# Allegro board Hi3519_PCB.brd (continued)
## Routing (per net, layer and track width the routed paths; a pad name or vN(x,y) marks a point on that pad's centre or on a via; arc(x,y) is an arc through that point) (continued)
DDR3_DQ19: length 16.4
  TOP w0.127: U3.B9 v1(87.2,57.29)
  ART04 w0.127: v1(82.7,70.32) 83.1,69.92 83.1,68.28 85.2,66.18 85.2,65.6 85.64,65.15 85.64,63.03 86.38,62.3 86.38,60.27 87.81,58.84 87.81,57.9 v1(87.2,57.29)
  BOTTOM w0.127: v1(82.7,70.32) U15.F8
DDR3_DQ20: length 14.8
  TOP w0.127: U3.C7 85.57,56.31 v1(85.25,55.99)
  ART03 w0.127: v1(85.25,55.99) 85.76,56.5 85.76,57.42 86.03,57.7 86.03,58.92 84.69,60.26 84.69,62.35 84.08,62.96 84.08,64.28 83.88,64.48 83.88,64.87 83.66,65.1 83.29,65.1 83.11,65.27 83.11,65.72 82.91,65.92 81.5,65.92 v1(81.1,66.32)
  BOTTOM w0.127: U15.H3 v1(81.1,66.32)
DDR3_DQ21: length 13.8
  TOP w0.127: U3.A4 v1(83.3,57.94)
  ART04 w0.127: v1(80.3,69.51) 80.3,68.71 80.72,68.3 80.72,63.77 82.36,62.13 82.36,59.97 83.3,59.03 v1(83.3,57.94)
  BOTTOM w0.127: v1(80.3,69.51) U15.H8
DDR3_DQ22: length 9.1
  TOP w0.127: U3.B3 v1(82.65,57.29)
  BOTTOM w0.127: v1(82.65,57.29) 82.48,57.46 82.48,59.35 81.13,60.7 81.13,64.74 U15.G2
DDR3_DQ23: length 14.7
  TOP w0.127: U3.C5 v1(84.6,56.64)
  ART04 w0.127: v1(81.92,67.6) 82.32,67.19 82.32,64.38 83.13,63.58 83.13,60.28 84.1,59.3 84.1,57.14 v1(84.6,56.64)
  BOTTOM w0.127: v1(81.92,67.6) 81.67,67.6 80.7,68.57 U15.H7
DDR3_DQ24: length 16.9
  TOP w0.127: U3.C10 v1(87.2,55.99)
  ART04 w0.127: v1(84.3,69.51) 84.74,69.08 84.74,68.68 87.2,66.21 87.2,60.57 88.55,59.22 88.55,57.34 v1(87.2,55.99)
  BOTTOM w0.127: v1(84.3,69.51) 83.9,69.11 U15.D7
DDR3_DQ25: length 14.4
  TOP w0.127: U3.C9 86.87,56.32 v1(87.2,56.64)
  ART04 w0.127: v1(87.2,56.64) 88.17,57.61 88.17,59.02 86.76,60.43 86.76,62.56 86.28,63.04 86.28,66.47 85.58,67.17 v1(84.99,67.17)
  BOTTOM w0.127: v1(84.99,67.17) 84.7,66.88 U15.C3
DDR3_DQ26: length 19.8
  TOP w0.127: U3.A9 v1(87.2,57.94)
  BOTTOM w0.127: U15.C8 85.12,70.33 85.12,71.26 85.5,71.64 86.26,71.64 87.15,70.75 87.15,68.33 89.72,65.76 89.72,59.79 87.86,57.94 v1(87.2,57.94)
DDR3_DQ27: length 9.3
  TOP w0.127: U3.B8 v1(86.55,57.29)
  ART04 w0.127: v1(86.55,57.29) 86.6,57.34 86.6,59.15 85.29,60.46 85.29,62.63 84.87,63.06 84.87,63.93 85.1,64.16 v1(85.1,64.71)
  BOTTOM w0.127: U15.C2 v1(85.1,64.71)
DDR3_DQ28: length 16.2
  TOP w0.127: U3.C6 84.92,56.31 v1(85.25,56.64)
  BOTTOM w0.127: U15.A7 86.3,68.1 88.95,65.45 88.95,60.11 87.84,58.99 86.77,58.99 86.52,58.74 86.52,58.33 85.8,57.62 85.8,57.19 v1(85.25,56.64)
DDR3_DQ29: length 9.5
  TOP w0.127: U3.B4 v1(83.3,57.29)
  BOTTOM w0.127: U15.A2 85.91,64.72 85.91,63.41 85.37,62.88 85.37,60.51 83.75,58.88 83.75,57.74 v1(83.3,57.29)
DDR3_DQ30: length 16.8
  TOP w0.127: v1(87.03,58.59) 86.22,57.79 U3.A8
  BOTTOM w0.127: v1(87.03,58.59) 87.97,58.59 89.34,59.95 89.34,65.6 86.77,68.17 86.77,69.99 86.49,70.27 85.86,70.27 U15.B8
DDR3_DQ31: length 13
  TOP w0.127: U3.C4 v1(83.3,55.99)
  BOTTOM w0.127: U15.A3 87.19,65.03 87.19,60.63 86.85,60.29 85.7,60.29 84.15,58.74 84.15,56.84 v1(83.3,55.99)
DDR3_DQS0_N: length 18.8
  TOP w0.109: U14.G3 81.76,68.86 81.76,68.5 82.23,68.03 82.64,68.03 82.8,67.87 82.8,67.61 82.96,67.45 83.18,67.45 83.34,67.61 83.34,67.87 83.5,68.03 87.21,68.03 90.17,65.08 90.17,57.66 U3.A14
DDR3_DQS0_P: length 18.8
  TOP w0.109: U3.B14 90.45,57.3 90.45,65.2 87.33,68.32 82.35,68.32 82.05,68.62 82.05,68.86 U14.F3
DDR3_DQS1_N: length 13.9
  TOP w0.109: U3.A12 88.86,57.65 88.86,62.51 88.72,62.65 88.44,62.65 88.3,62.8 88.3,63 88.44,63.14 88.72,63.14 88.86,63.28 88.86,63.49 88.72,63.63 88.44,63.63 88.3,63.78 88.3,63.98 88.44,64.12 88.75,64.12 88.86,64.23 88.86,64.45 86.6,66.71 85.56,66.71 85.19,66.34 85.19,66.01 85.28,65.92 U14.B7
DDR3_DQS1_P: length 13.9
  TOP w0.109: U3.B12 89.14,57.29 89.14,64.57 86.72,66.99 85.44,66.99 84.9,66.46 84.9,65.99 84.83,65.92 U14.C7
DDR3_DQS2_N: length 10.7
  TOP w0.102: U3.A7 v1(85.25,57.94)
  ART03 w0.102: v1(81.9,65.52) 82.1,65.52 82.27,65.35 82.27,63.47 82.58,63.16 82.58,61.19 83.89,59.88 83.89,59.68 83.77,59.55 83.77,59.38 83.94,59.21 84.11,59.21 84.23,59.34 84.43,59.34 85.31,58.46 85.31,58 v1(85.25,57.94)
  BOTTOM w0.114: U15.G3 v1(81.9,65.52)
DDR3_DQS2_P: length 10.7
  TOP w0.102: U3.B7 v1(85.25,57.29)
  ART03 w0.102: v1(85.25,57.29) 85.25,57.42 85.62,57.79 85.62,58.59 82.89,61.32 82.89,63.29 82.58,63.6 82.58,65.39 v1(82.7,65.51)
  BOTTOM w0.114: U15.F3 v1(82.7,65.51)
DDR3_DQS3_N: length 16.4
  TOP w0.102: U3.A5 v1(84.6,57.94)
  BOTTOM w0.109: v1(84.6,57.94) 84.6,58.02 85.1,58.51 85.3,58.51 85.45,58.36 85.66,58.36 85.8,58.5 85.8,58.71 85.65,58.86 85.65,59.06 86.08,59.49 87.45,59.49 88.46,60.5 88.46,65.21 85.15,68.51 85.15,69.01 85.26,69.11 U15.B7
DDR3_DQS3_P: length 16.4
  TOP w0.102: U3.B5 83.97,57.27 83.97,57.96 v1(84.6,58.59)
  BOTTOM w0.109: v1(84.6,58.59) 84.77,58.59 84.83,58.65 85.96,59.78 87.33,59.78 88.17,60.62 88.17,65.09 84.87,68.39 84.87,68.95 U15.C7
DDR3_ODT: length 20.9
  TOP w0.127: U3.D3 v1(82.65,55.99) ; v1(79.2,67.13) 78.82,67.51 78.82,68.82 78.73,68.9 78.73,70.35 U14.K1
  ART04 w0.127: v1(82.65,55.99) 81.73,56.91 81.19,56.91 79.74,58.36 79.74,60.85 80.02,61.13 80.02,63.29 78.9,64.4 78.9,66.59 79.2,66.89 v1(79.2,67.13)
  BOTTOM w0.127: v1(79.2,67.13) 79.2,66.96 78.71,66.47 78.71,64.97 79.1,64.58 U15.K1
DDR3_RAS_N: length 20.3
  TOP w0.127: v1(79.96,67.9) 79.9,67.95 U14.J3 ; U3.D4 v1(83.3,55.34)
  ART03 w0.127: v1(79.96,67.9) 79.58,67.51 79.58,66.94 79.12,66.48 79.12,64.43 80.22,63.34 80.22,60.52 80.71,60.02 80.71,58.52 80.55,58.36 80.55,57.55 81.44,56.66 83.34,56.66 83.7,56.3 83.7,55.74 v1(83.3,55.34)
  BOTTOM w0.127: v1(79.96,67.9) 80.38,67.47 80.38,66.94 79.92,66.47 79.92,65.93 U15.J3
DDR3_RESET_N: length 31.4
  TOP w0.127: v1(70.81,67.13) 70.81,67.34 71.2,67.72 71.2,68.09 73.02,69.92 U14.T2 ; U3.H3 v1(82.65,53.39)
  ART04 w0.127: v1(82.65,53.39) 82,52.75 79.08,52.75 72.32,59.5 72.32,64.89 70.81,66.39 v1(70.81,67.13)
  BOTTOM w0.127: v1(70.81,67.13) 72.83,65.11 U15.T2
DDR3_WE_N: length 18
  TOP w0.127: U3.C2 v1(82,55.99) ; U14.L3 78.43,68.98 v1(78.43,67.9)
  ART04 w0.127: v1(78.43,67.9) 78.05,67.51 78.05,64.61 78.72,63.95 78.72,58.89 81.21,56.4 81.59,56.4 v1(82,55.99)
  BOTTOM w0.127: v1(78.43,67.9) 78.82,67.51 78.82,66.95 78.3,66.44 U15.L3
DRIVE+: length 18.2
  BOTTOM w0.127: LB12.2 R165.2 67.09,78.12 65.94,79.26 65.94,82.2 J26.2
DRIVING+_G: length 2.3
  BOTTOM w0.127: R32.2 C1.1 LB12.1
EPHY_CLK: length 27.3
  TOP w0.127: R216.1 129.42,74.92 v2(129.82,75.33)
  ART04 w0.127: v2(129.82,75.33) 129.8,75.3 129.8,70.86 127.44,68.49 111.82,68.49 v2(111.28,67.96)
  BOTTOM w0.127: U10.48 110.95,68.29 v2(111.28,67.96)
EPHY_CLK/VO_DATA8: length 21.2
  ART03 w0.127: v2(99.22,60.34) 99.09,60.34 98.46,60.97 98.46,68.09 99.09,68.72 103.66,68.72 v2(104.3,68.09)
  BOTTOM w0.127: R21.1 95,57.96 96.7,59.67 98.54,59.67 v2(99.22,60.34) ; v2(104.3,68.09) 104.3,68.21 104.87,68.79 U10.2
EPHY_RSTN/SPI_NAND_SEL: length 41.2
  TOP w0.127: U2.29 122.56,69.38 122.56,69.38 122.56,69.25 122.12,68.81 120.97,68.81 120.81,68.98 C213.1 120.32,68.55 120.07,68.29 117.44,68.29 113.96,64.81 101.53,64.81 v2(99.22,62.5) ; U3.D16 v1(91.75,55.99)
  BOTTOM w0.127: v1(91.75,55.99) 90.94,56.8 R558.2 R87.1 92.7,58.84 96.36,62.5 v2(99.22,62.5)
FLASH_TRIG: length 35.7
  TOP w0.127: U3.W15 v1(90.45,46.24) ; J18.62 v2(121.39,38.6)
  ART03 w0.127: v2(121.39,38.6) 116.45,43.54 102.1,43.54 101.21,44.43 99.63,44.43 98.71,45.35 91.97,45.35 91.09,46.24 v1(90.45,46.24)
FLASH_TRIG_C: length 16.8
  TOP w0.127: R185.1 R59.1 34.4,63.9 v2(38.13,63.9)
  BOTTOM w0.127: J19.62 40.92,55.4 38.05,58.26 38.05,63.82 v2(38.13,63.9)
FLASH_TRIG_COM: length 17.5
  TOP w0.127: K1.3 19.26,71.82 18.7,71.26 J17.10 J17.9
FLASH_TRIG_NO: length 12.9
  TOP w0.127: J17.7 J17.8 16.79,73.8 17.06,74.07 K1.4
HOT_PLUG_SII9022A: length 17.4
  TOP w0.127: R37.2 140.44,42.33 R68.2 C79.2 148.11,43.58 148.69,44.15 U17.4 151.1,44.15 152.63,45.68 J28.19
I2C3_SCL: length 111.1
  TOP w0.127: U22.1 139.22,57.54 v2(139.22,57.55) 139.22,58.13 140.11,59.02 R53.1 ; U3.AB17 91.86,43.76 91.86,39.73 v2(93.2,38.39)
  ART03 w0.127: v2(93.2,38.39) 94.45,37.14 108.02,37.14 120.02,25.14 127.54,25.14 129.65,23.03 145.98,23.03 148.84,25.88 148.84,47.51 147.99,48.36 147.99,52.72 144.18,56.53 141.2,56.53 140.18,57.55 v2(139.22,57.55)
I2C3_SDA: length 113.7
  TOP w0.127: U22.2 138.72,58.85 v2(139.07,59.2) 139.1,59.22 R52.1 ; U3.AB16 91.48,43.91 91.48,39.12 v2(93.17,37.43)
  ART03 w0.127: v2(93.17,37.43) 93.84,36.76 107.86,36.76 119.86,24.75 127.38,24.75 129.49,22.65 146.14,22.65 149.22,25.73 149.22,47.67 148.37,48.52 148.37,52.97 144.43,56.91 141.36,56.91 v2(139.07,59.2)
IO3V3_SII9022A: length 21.1
  TOP w0.254: U22.3 v2(138.22,57.55) ; U22.46 135.22,45.86 135.03,45.67 135.03,45.35 ; U22.21 v2(128.94,54.8)
  TOP w0.381: v2(134.14,44.46) 134.24,44.36 C71.1 135.03,45.35 ; R150.2 v2(142.91,57.67)
  ART03 w0.381: v2(128.94,54.8) 129.7,54.04 129.7,50.05 134.14,45.61 v2(134.14,44.46)
  BOTTOM w0.305: 128.69,54.78 C73.1 128.17,55.3 ; 138.21,58.02 C72.1 ; C72.1 138.73,58.54 ; C72.1 137.69,58.54
IRCUT_CONTROL1: length 62.7
  TOP w0.127: J1.76 56.55,53 56.49,53.05 55.58,53.05 54.51,51.99 54.51,44.11 52.86,42.46 52.86,38.72 56.79,34.79 85.76,34.79 90.63,39.66 90.63,41.83 90.77,41.98 U3.AB15
IRCUT_CONTROL2: length 63.8
  TOP w0.127: v2(56.16,53.61) 56.38,53.4 J1.78 ; U3.AA17 92.07,44.61 v1(91.75,44.29)
  ART03 w0.127: v2(56.16,53.61) 56.55,53.23 56.55,41.67 54.77,39.89 54.77,37.86 60.61,32.02 81.7,32.02 90.12,40.45 90.12,41.9 91.75,43.52 v1(91.75,44.29)
IRIS_5V0: length 3.8
  TOP w0.381: C86.1 v2(81.31,80.28)
  BOTTOM w0.381: 79.79,79.52 78.39,78.12 R165.1
JTAG_EN: length 56.4
  TOP w0.127: U3.K2 82,51.44 80.47,51.44 80.2,51.7 78.64,51.7 v1(78.39,51.45) ; SW2.2 v2(89.32,76.46)
  ART03 w0.127: v1(78.39,51.45) 77.4,51.45 76.64,52.21 75.85,52.21 68.48,59.58 68.48,73.17 72.55,77.23 88.55,77.23 v2(89.32,76.46)
  BOTTOM w0.127: R65.2 v2(89.32,76.46)
JTAG_RSTN: length 49
  TOP w0.127: U3.L2 81.99,50.78 v1(81.34,50.78)
  ART04 w0.127: v1(81.34,50.78) 81.15,50.59 78.43,50.59 76.17,48.33 76.17,42.15 75.09,41.07 75.09,29.64 77.5,27.23 77.5,25.7 80.88,22.32 80.88,9.78 J21.3
JTAG_TCK: length 100.8
  TOP w0.127: U3.L1 81.62,51.16 80.33,51.16 80.04,51.45 79.41,51.45 v1(79.02,51.07)
  ART03 w0.127: J21.6 84.39,11.7 81.85,14.24 61.24,14.24 58.7,16.78 58.7,33.38 54.39,37.7 54.39,40.05 55.53,41.19 55.53,55.86 56.83,57.16 70.36,57.16 75.82,51.7 76.61,51.7 77.25,51.07 v1(79.02,51.07)
JTAG_TDI: length 50.4
  TOP w0.127: U3.L4 v1(83.95,51.44)
  ART04 w0.127: J21.4 81.69,9.73 81.69,22.59 78.26,26.02 78.26,27.54 75.93,29.88 75.93,40.45 76.93,41.46 76.93,48.01 78.18,49.27 80.98,49.27 82.4,50.69 83.47,50.69 83.95,51.17 v1(83.95,51.44)
JTAG_TDO: length 55.4
  TOP w0.127: U3.L3 v1(83.3,51.44)
  ART04 w0.127: J21.7 84.75,8.65 81.56,8.65 81.26,8.96 81.26,22.48 77.88,25.86 77.88,27.39 75.54,29.72 75.54,40.61 76.55,41.61 76.55,48.17 78.58,50.21 81.36,50.21 82.21,51.06 82.92,51.06 v1(83.3,51.44)
JTAG_TMS: length 47.8
  TOP w0.127: U3.M3 v1(82.65,50.14)
  ART04 w0.127: v1(82.65,50.14) 82.39,50.14 81.13,48.88 79.1,48.88 77.99,47.78 77.99,47.01 77.31,46.33 77.31,41.28 76.36,40.32 76.36,29.99 78.64,27.7 78.64,26.18 82.07,22.75 82.07,10.6 J21.5
LED0_ACTIVE/PHY_AD0: length 33.1
  TOP w0.127: U2.34 124.56,69.86 124.35,69.66 124.35,67.39 124.54,67.2 R142.1 124.54,66.44 128.48,62.5 v2(137.32,62.5)
  BOTTOM w0.127: v2(137.32,62.5) 144.8,62.5 J20.15
LED1_LINK/PHY_AD1: length 11.9
  TOP w0.127: U2.35 124.96,68.61 R143.1 124.97,67.6 125.25,67.32 125.25,66.56 128.55,63.26 R4.1
MDCK: length 32.7
  TOP w0.127: U2.30 122.96,69.12 122.15,68.3 120.8,68.3 120.28,67.78 117.65,67.78 114.17,64.3 102.04,64.3 v2(99.22,61.48)
  BOTTOM w0.127: R800.1 97.06,61.48 v2(99.22,61.48)
MDIN0: length 26.7
  TOP w0.109: v2(132.71,74.57) 133,74.86 133.78,74.86 134.14,74.5 T1.3 ; v2(125.57,79.45) 125.85,79.16 125.85,78.24 125.02,77.4 125.02,76.76 124.96,76.71 U2.2
  ART03 w0.102: v2(125.57,79.45) 125.71,79.31 125.71,78.98 126.12,78.58 128,78.58 128.33,78.91 128.33,79.95 128.53,80.15 130.74,80.15 131.52,79.37 132.83,79.37 133.05,79.15 133.05,78.85 132.83,78.63 131.67,78.63 131.27,78.24 131.27,77.68 131.67,77.29 132.83,77.29 133.05,77.07 133.05,76.77 132.83,76.55 131.67,76.55 131.27,76.16 131.27,75.1 131.62,74.74 132.53,74.74 v2(132.71,74.57)
MDIN1: length 26.1
  TOP w0.109: v2(132.96,71.57) 133.25,71.86 133.78,71.86 134.14,71.5 T1.6 ; v2(124.04,80.09) 124.33,79.81 124.33,77.99 123.82,77.48 123.82,76.76 123.76,76.71 U2.5
  ART03 w0.102: v2(124.04,80.09) 124.22,79.92 124.22,78.87 125.91,77.18 128.73,77.18 129.19,77.64 129.19,78.96 129.44,79.21 130.1,79.21 130.36,78.96 130.36,74.67 131.35,73.67 131.35,72.28 131.86,71.77 132.76,71.77 v2(132.96,71.57)
MDIN2: length 26.5
  TOP w0.109: v2(122.33,79.26) 122.62,78.97 122.62,76.76 122.56,76.71 U2.8 ; v2(132.83,68.57) 133.12,68.86 133.78,68.86 134.14,68.5 T1.9
  ART03 w0.102: v2(132.83,68.57) 132.66,68.74 131.78,68.74 131.3,69.23 131.3,70.5 130.97,70.83 130.21,70.83 129.52,71.52 129.52,73.62 128.71,74.44 128.71,75.66 128.48,75.88 127.56,75.88 127.36,75.68 127.36,75.2 127.01,74.84 126.32,74.84 125.94,75.22 125.94,76.01 125.74,76.21 123.73,76.21 122.48,77.46 122.48,79.11 v2(122.33,79.26)
MDIN3: length 26.8
  TOP w0.109: v2(133.09,65.57) 133.38,65.86 133.78,65.86 134.14,65.5 T1.12 ; v2(120.39,79.15) 120.68,78.86 120.68,78.12 121.42,77.38 121.42,76.73 121.36,76.67 U2.11
  ART03 w0.102: v2(120.39,79.15) 120.57,78.97 120.57,77.44 122.84,75.17 124.59,75.17 126.35,73.42 127.25,73.42 128.38,72.3 128.38,69.92 132.55,65.74 132.91,65.74 v2(133.09,65.57)
MDIO: length 39.5
  TOP w0.127: U2.31 123.36,68.98 122.09,67.71 v2(121.06,67.71) 120.76,67.4 117.81,67.4 114.33,63.92 102.42,63.92 99.42,60.92 98.76,60.92 v2(97.97,60.14) ; U3.D17 v1(92.4,55.99)
  BOTTOM w0.127: R102.1 120.96,67.6 v2(121.06,67.71) ; v1(92.4,55.99) 92.84,56.43 92.84,56.73 94.72,58.61 94.92,58.61 96.45,60.14 v2(97.97,60.14)
MDIP0: length 26.7
  TOP w0.109: v2(126.43,79.45) 126.14,79.16 126.14,78.12 125.3,77.28 125.3,76.78 125.36,76.72 U2.1 ; T1.2 134.14,75.5 133.78,75.14 133,75.14 v2(132.71,75.43)
  ART03 w0.102: v2(132.71,75.43) 132.71,75.19 132.57,75.05 131.75,75.05 131.58,75.22 131.58,76.03 131.79,76.25 132.96,76.25 133.36,76.64 133.36,77.2 132.96,77.59 131.79,77.59 131.58,77.81 131.58,78.11 131.79,78.33 132.96,78.33 133.36,78.72 133.36,79.28 132.96,79.68 131.65,79.68 130.87,80.46 128.4,80.46 128.02,80.08 128.02,79.03 127.87,78.88 126.24,78.88 126.01,79.11 126.01,79.35 126.12,79.45 v2(126.43,79.45)
MDIP1: length 25.9
  TOP w0.109: U2.4 124.16,76.71 124.1,76.76 124.1,77.36 124.62,77.87 124.62,79.81 v2(124.91,80.09) ; T1.5 134.14,72.5 133.78,72.14 133.25,72.14 v2(132.96,72.43)
  ART03 w0.102: v2(124.91,80.09) 124.64,80.09 124.52,79.97 124.52,79 125.99,77.54 128.66,77.54 128.88,77.76 128.88,79.09 129.32,79.52 130.23,79.52 130.66,79.09 130.66,74.79 131.65,73.8 131.65,72.4 131.98,72.08 132.82,72.08 132.96,72.21 v2(132.96,72.43)
MDIP2: length 26.5
  TOP w0.109: U2.7 122.96,76.71 122.9,76.76 122.9,78.97 v2(123.19,79.26) ; T1.8 134.14,69.5 133.78,69.14 133.12,69.14 v2(132.83,69.43)
  ART03 w0.102: v2(123.19,79.26) 122.94,79.26 122.79,79.11 122.79,77.59 123.85,76.52 125.86,76.52 126.24,76.14 126.24,75.35 126.45,75.15 126.88,75.15 127.06,75.33 127.06,75.81 127.44,76.19 128.61,76.19 129.01,75.78 129.01,74.56 129.82,73.75 129.82,71.64 130.33,71.13 131.09,71.13 131.6,70.63 131.6,69.36 131.91,69.05 132.72,69.05 132.83,69.16 v2(132.83,69.43)
MDIP3: length 26.8
  TOP w0.109: v2(121.26,79.15) 120.97,78.86 120.97,78.24 121.7,77.5 121.7,76.75 121.76,76.7 U2.10 ; T1.11 134.14,66.5 133.78,66.14 133.38,66.14 v2(133.09,66.43)
  ART03 w0.102: v2(133.09,66.43) 133.09,66.16 132.97,66.05 132.67,66.05 128.68,70.04 128.68,72.42 127.38,73.73 126.47,73.73 124.72,75.48 122.97,75.48 120.87,77.57 120.87,79.03 120.99,79.15 v2(121.26,79.15)
MIPI0_CKM: length 61
  TOP w0.109: v2(62.94,42.83) 62.88,42.83 62.31,42.25 60.81,42.25 60.75,42.2 J1.21
  TOP w0.114: U3.Y6 v1(84.6,44.94)
  ART03 w0.102: v2(62.94,42.83) 62.66,42.83 62.44,42.61 62.44,42.23 61.88,41.67 61.88,38.29 62.25,37.92 76.39,37.92 76.55,38.08 76.55,45.86 76.85,46.17 77.33,46.17 77.64,45.86 77.64,39.27 77.78,39.13 77.98,39.13 78.12,39.27 78.12,45.86 78.43,46.17 78.89,46.17 79.21,45.85 79.21,41.81 79.36,41.67 84.42,41.67 84.69,41.94 84.69,42.31 84.43,42.57 84.43,42.92 84.69,43.18 84.69,43.53 84.43,43.79 84.43,44.14 84.69,44.4 84.69,44.85 v1(84.6,44.94)
MIPI0_CKP: length 61
  TOP w0.109: v2(62.02,42.83) 61.73,42.54 60.81,42.54 60.75,42.6 J1.23
  TOP w0.114: U3.W6 v1(84.6,45.59)
  ART03 w0.102: v2(62.02,42.83) 62.13,42.72 62.13,42.36 61.57,41.8 61.57,38.17 62.13,37.61 76.52,37.61 76.85,37.95 76.85,45.73 76.98,45.86 77.21,45.86 77.33,45.73 77.33,39.15 77.65,38.83 78.11,38.83 78.43,39.15 78.43,45.73 78.55,45.86 78.77,45.86 78.91,45.72 78.91,41.69 79.23,41.37 84.55,41.37 84.99,41.81 84.99,45.06 84.6,45.46 v1(84.6,45.59)
MIPI0_D0M: length 54.1
  TOP w0.109: v2(70.4,42.86) 70.19,42.65 70.19,40.8 70.36,40.62 83.11,40.62 85.24,42.76 85.24,44.28 U3.AA7 ; J1.9 60.75,39.8 60.81,39.85 62.11,39.85 v2(62.4,39.56)
  ART03 w0.102: v2(62.4,39.56) 62.4,39.74 62.53,39.87 64.64,39.87 64.97,40.2 64.97,42.66 65.14,42.83 65.28,42.83 65.45,42.66 65.45,39.51 65.77,39.19 66.22,39.19 66.54,39.51 66.54,42.8 66.66,42.92 66.91,42.92 67.03,42.8 67.03,39.51 67.35,39.19 67.8,39.19 68.12,39.51 68.12,42.81 68.22,42.92 68.48,42.92 68.6,42.8 68.6,39.53 68.92,39.21 69.94,39.21 70.22,39.49 70.22,42.69 v2(70.4,42.86)
MIPI0_D0P: length 54.1
  TOP w0.109: v2(69.53,42.86) 69.78,42.86 69.9,42.75 69.9,40.68 70.24,40.33 83.22,40.33 85.53,42.64 85.53,43.92 U3.AB7 ; v2(62.4,40.43) 62.11,40.14 60.81,40.14 60.75,40.2 J1.11
  ART03 w0.102: v2(62.4,40.43) 62.66,40.17 64.51,40.17 64.66,40.32 64.66,42.79 65.01,43.14 65.41,43.14 65.76,42.79 65.76,39.64 65.9,39.49 66.1,39.49 66.24,39.64 66.24,42.93 66.53,43.22 67.04,43.22 67.33,42.92 67.33,39.64 67.47,39.49 67.67,39.49 67.81,39.64 67.81,42.94 68.09,43.22 68.61,43.22 68.91,42.92 68.91,39.65 69.05,39.51 69.81,39.51 69.91,39.61 69.91,42.73 69.78,42.86 v2(69.53,42.86)
MIPI0_D1M: length 54.7
  TOP w0.109: J1.3 60.75,38.6 60.81,38.65 61.65,38.65 61.83,38.47 61.83,37.43 61.68,37.27 57.88,37.27 57.54,36.92 57.54,36.43 57.88,36.08 63.91,36.08 64.24,36.41 64.24,37.05 63.91,37.38 63.28,37.38 63.1,37.56 63.1,38.54 63.21,38.65 63.37,38.65 v2(63.66,38.36) ; v2(71.73,41.9) 71.5,41.67 71.5,41.53 71.62,41.4 82.78,41.4 84.59,43.21 84.59,44.28 U3.AA6
  ART03 w0.102: v2(71.73,41.9) 71.51,41.68 71.51,39.74 71.73,39.51 75.77,39.51 76.06,39.22 76.06,38.69 75.78,38.4 65.05,38.4 64.81,38.64 63.94,38.64 v2(63.66,38.36)
MIPI0_D1P: length 54.8
  TOP w0.109: v2(70.86,41.9) 71.05,41.9 71.21,41.74 71.21,41.41 71.5,41.11 82.9,41.11 84.88,43.09 84.88,43.92 U3.AB6 ; J1.5 60.75,39 60.81,38.94 61.77,38.94 62.12,38.59 62.12,37.31 61.8,36.98 58,36.98 57.82,36.8 57.82,36.55 58,36.37 63.79,36.37 63.95,36.53 63.95,36.93 63.79,37.09 63.16,37.09 62.81,37.44 62.81,38.66 63.09,38.94 63.37,38.94 v2(63.66,39.23)
  ART03 w0.102: v2(70.86,41.9) 71.08,41.9 71.2,41.77 71.2,39.61 71.61,39.21 75.65,39.21 75.76,39.09 75.76,38.81 75.65,38.71 65.17,38.71 64.93,38.95 63.94,38.95 v2(63.66,39.23)
MIPI0_D2M: length 53.5
  TOP w0.109: v2(64.09,44.23) 63.84,43.98 63.84,43.73 63.56,43.45 60.73,43.45 60.68,43.4 J1.27
  TOP w0.114: U3.W8 v1(85.9,45.59)
  ART03 w0.102: v1(85.9,45.59) 85.9,45.46 85.53,45.09 85.53,41.66 84.75,40.88 80.82,40.88 80.48,40.55 80.48,38.82 80.34,38.67 80.14,38.67 80,38.82 80,40.58 79.7,40.88 79.2,40.88 78.91,40.59 78.91,37.27 78.77,37.13 78.57,37.13 78.43,37.27 78.43,38.01 78.11,38.33 77.65,38.33 77.33,38.01 77.33,37.27 77.19,37.13 61.41,37.13 60.42,38.12 60.42,43.34 60.53,43.44 63.53,43.44 63.89,43.8 63.89,44.03 v2(64.09,44.23)
MIPI0_D2P: length 53.5
  TOP w0.109: J1.29 60.68,43.8 60.73,43.74 63.44,43.74 63.55,43.85 63.55,44 63.32,44.23 v2(63.23,44.23)
  TOP w0.114: U3.Y8 v1(85.9,44.94)
  ART03 w0.102: v1(85.9,44.94) 85.83,44.88 85.83,41.54 84.88,40.58 80.95,40.58 80.79,40.42 80.79,38.69 80.47,38.37 80.02,38.37 79.7,38.69 79.7,40.45 79.57,40.58 79.33,40.58 79.21,40.46 79.21,37.14 78.9,36.83 78.44,36.83 78.12,37.15 78.12,37.88 77.98,38.03 77.78,38.03 77.64,37.88 77.64,37.15 77.32,36.83 61.28,36.83 60.11,38 60.11,43.46 60.4,43.75 63.4,43.75 63.58,43.93 63.58,44.08 63.43,44.23 v2(63.23,44.23)
MIPI0_D3M: length 54
  TOP w0.109: U3.AA5 83.94,44.28 83.94,43.57 82.55,42.18 74.63,42.18 74.31,42.5 74.31,45.48 74,45.79 73.52,45.79 73.24,45.51 73.24,42.28 73.14,42.18 72.88,42.18 72.75,42.31 72.75,46.16 v2(73.04,46.45) ; J1.15 60.75,41 60.81,41.05 63.12,41.05 v2(63.4,40.76)
  ART03 w0.102: v2(63.4,40.76) 63.67,41.03 63.9,41.03 64.18,41.31 64.18,42.99 64.9,43.7 71.44,43.7 71.58,43.56 71.58,42.8 71.9,42.48 72.35,42.48 72.67,42.8 72.67,43.93 72.8,44.06 73.03,44.06 73.16,43.93 73.16,40.27 73.44,39.99 73.97,39.99 74.25,40.27 74.25,45.38 73.84,45.79 72.89,45.79 72.76,45.91 72.76,46.17 v2(73.04,46.45)
MIPI0_D3P: length 54
  TOP w0.109: v2(63.4,41.68) 63.4,41.47 63.28,41.34 60.81,41.34 60.75,41.4 J1.17 ; v2(72.18,46.45) 72.46,46.16 72.46,42.19 72.76,41.89 73.26,41.89 73.53,42.16 73.53,45.39 73.64,45.5 73.88,45.5 74.02,45.36 74.02,42.38 74.51,41.89 82.67,41.89 84.23,43.45 84.23,43.92 U3.AB5
  ART03 w0.102: v2(72.18,46.45) 72.45,46.17 72.45,45.79 72.76,45.48 73.72,45.48 73.94,45.25 73.94,40.4 73.84,40.3 73.56,40.3 73.46,40.4 73.46,44.06 73.16,44.36 72.67,44.36 72.37,44.06 72.37,42.93 72.23,42.79 72.03,42.79 71.89,42.93 71.89,43.69 71.57,44.01 64.77,44.01 63.88,43.11 63.88,41.44 63.78,41.34 63.51,41.34 63.4,41.44 v2(63.4,41.68)
MIPI1_CKM: length 58.6
  TOP w0.109: v2(61.88,47.63) 61.59,47.34 60.81,47.34 60.75,47.4 J1.47
  TOP w0.114: U3.W9 v1(86.55,45.59)
  ART03 w0.102: v2(61.88,47.63) 61.6,47.35 59.68,47.35 59.34,47 59.34,46.27 59.69,45.91 59.92,45.91 60.1,45.73 60.1,45.48 59.92,45.3 59.69,45.3 59.34,44.94 59.34,37.66 60.96,36.04 79.68,36.04 80,36.36 80,37.44 80.14,37.58 80.34,37.58 80.48,37.44 80.48,36.36 80.8,36.04 81.26,36.04 81.58,36.36 81.58,39.62 81.72,39.77 81.92,39.77 82.06,39.62 82.06,37.76 82.38,37.44 82.83,37.44 83.15,37.76 83.15,39.4 83.55,39.79 85.2,39.79 86.92,41.5 86.92,45.09 86.55,45.46 v1(86.55,45.59)
MIPI1_CKP: length 58.5
  TOP w0.109: v2(62.87,47.63) 62.29,47.05 60.81,47.05 60.75,47 J1.45
  TOP w0.114: U3.Y9 v1(86.55,44.94)
  ART03 w0.102: v1(86.55,44.94) 86.61,44.88 86.61,41.63 85.08,40.1 83.42,40.1 82.85,39.52 82.85,37.88 82.71,37.74 82.51,37.74 82.36,37.88 82.36,39.75 82.04,40.07 81.59,40.07 81.27,39.75 81.27,36.49 81.13,36.34 80.93,36.34 80.79,36.49 80.79,37.57 80.47,37.89 80.02,37.89 79.7,37.57 79.7,36.49 79.56,36.34 61.08,36.34 59.64,37.79 59.64,44.82 59.82,45 60.05,45 60.41,45.35 60.41,45.86 60.05,46.22 59.82,46.22 59.64,46.39 59.64,46.87 59.81,47.04 62.29,47.04 v2(62.87,47.63)
MIPI1_D0M: length 53.7
  TOP w0.109: J1.53 60.68,48.6 60.74,48.54 63.78,48.54 v2(64.06,48.83) ; U3.AB10 87.48,43.92 87.48,41.27 84.21,38 67.6,38 67.13,38.47 67.13,47 67.44,47.31 69.37,47.31 69.52,47.45 69.52,47.65 69.37,47.8 67.41,47.8 67.13,48.07 67.13,49.24 67.42,49.53 67.99,49.53 v2(68.2,49.74)
  ART03 w0.102: v2(68.2,49.74) 67.96,49.49 67.39,49.49 67.29,49.6 67.29,50.15 66.98,50.46 66.5,50.46 66.2,50.15 66.2,49.24 66.07,49.11 65.84,49.11 65.71,49.24 65.71,50.15 65.41,50.46 64.93,50.46 64.62,50.15 64.62,48.83 64.47,48.68 64.21,48.68 v2(64.06,48.83)
MIPI1_D0P: length 53.7
  TOP w0.109: U3.AA10 87.19,44.28 87.19,41.39 84.09,38.29 67.72,38.29 67.42,38.59 67.42,46.88 67.56,47.02 69.49,47.02 69.8,47.33 69.8,47.77 69.49,48.08 67.53,48.08 67.42,48.19 67.42,49.12 67.54,49.24 68.08,49.24 68.2,49.12 v2(68.2,48.88) ; J1.51 60.62,48.2 60.68,48.25 63.78,48.25 v2(64.06,47.96)
  ART03 w0.102: v2(64.06,47.96) 64.06,48.25 64.19,48.38 64.6,48.38 64.93,48.71 64.93,50.03 65.05,50.15 65.28,50.15 65.41,50.03 65.41,49.11 65.72,48.81 66.2,48.81 66.5,49.11 66.5,50.03 66.63,50.15 66.86,50.15 66.98,50.03 66.98,49.47 67.26,49.19 68.05,49.19 68.2,49.04 v2(68.2,48.88)
MIPI1_D1M: length 53.9
  TOP w0.109: v2(63.16,46.66) 63.26,46.66 63.45,46.48 63.45,46.26 63.33,46.14 60.74,46.14 60.68,46.2 J1.41 ; U3.AB9 86.83,43.92 86.83,41.72 83.89,38.78 68.33,38.78 67.91,39.2 67.91,45.64 68.2,45.93 68.2,46.12 v2(67.91,46.41)
  ART03 w0.102: v2(63.16,46.66) 63.42,46.66 63.53,46.55 63.53,45.84 63.81,45.56 64.72,45.56 65.05,45.88 65.05,47.72 65.17,47.83 65.42,47.83 65.53,47.72 65.53,46.65 65.82,46.37 66.35,46.37 66.63,46.65 66.63,47.87 66.78,48.02 72.01,48.02 72.17,47.87 72.17,47.56 72.01,47.41 68.51,47.41 68.19,47.09 68.19,46.69 v2(67.91,46.41)
MIPI1_D1P: length 53.9
  TOP w0.109: J1.39 60.62,45.8 60.68,45.85 63.45,45.85 63.73,46.14 63.73,46.37 v2(64.02,46.66) ; U3.AA9 86.54,44.28 86.54,41.84 83.77,39.07 68.45,39.07 68.2,39.32 68.2,45.52 68.48,45.81 68.48,46.12 v2(68.77,46.41)
  ART03 w0.102: v2(68.77,46.41) 68.49,46.69 68.49,46.96 68.64,47.11 72.14,47.11 72.47,47.44 72.47,48 72.14,48.33 66.65,48.33 66.32,48 66.32,46.77 66.22,46.67 65.94,46.67 65.84,46.78 65.84,47.84 65.54,48.14 65.04,48.14 64.75,47.84 64.75,46.01 64.6,45.86 63.94,45.86 63.84,45.96 63.84,46.48 v2(64.02,46.66)
MIPI1_D2M: length 54.5
  TOP w0.109: J1.59 60.75,49.8 60.81,49.74 62.38,49.74 62.72,50.08 63.04,50.08 v2(63.33,50.37) ; v2(66.84,52.05) 66.97,52.05 67.18,51.84 67.18,51.48 67.48,51.19 68.14,51.19 68.27,51.05 68.27,50.83 68.14,50.7 66.71,50.7 66.35,50.34 66.35,37.97 67.1,37.23 84.53,37.23 88.13,40.82 88.13,43.92 U3.AB11
  ART03 w0.102: v2(66.84,52.05) 66.97,52.05 67.17,51.85 67.17,51.38 67.04,51.25 66.31,51.25 66.17,51.39 66.17,52.02 65.85,52.34 65.4,52.34 65.08,52.02 65.08,51.39 64.94,51.25 64.34,51.25 63.84,50.74 63.84,50.15 63.73,50.05 63.44,50.05 63.33,50.16 v2(63.33,50.37)
MIPI1_D2P: length 54.5
  TOP w0.109: v2(63.33,49.5) 63.04,49.79 62.84,49.79 62.5,49.45 60.81,49.45 60.75,49.4 J1.57 ; U3.AA11 87.84,44.28 87.84,40.94 84.41,37.51 67.22,37.51 66.64,38.09 66.64,50.22 66.83,50.41 68.25,50.41 68.56,50.71 68.56,51.17 68.26,51.47 67.6,51.47 67.47,51.6 67.47,51.81 v2(67.7,52.05)
  ART03 w0.102: v2(63.33,49.5) 63.33,49.63 63.44,49.74 63.85,49.74 64.14,50.03 64.14,50.61 64.47,50.94 65.06,50.94 65.38,51.26 65.38,51.89 65.52,52.03 65.73,52.03 65.87,51.89 65.87,51.26 66.19,50.94 67.16,50.94 67.48,51.26 67.48,51.82 v2(67.7,52.05)
MIPI1_D3M: length 53.9
  TOP w0.109: U3.AB8 86.18,43.92 86.18,42.19 83.55,39.56 69.17,39.56 68.69,40.05 68.69,43.43 69.06,43.8 71.55,43.8 71.69,43.93 71.69,44.16 71.56,44.29 68.97,44.29 68.69,44.57 68.69,45.07 68.97,45.36 70.18,45.36 70.4,45.58 70.4,46.31 70.26,46.45 v2(70.01,46.45) ; J1.35 60.75,45 60.81,44.94 61.69,44.94 v2(61.98,45.23)
  ART03 w0.102: v2(70.01,46.45) 70.11,46.45 70.34,46.22 70.34,45.74 70.69,45.38 71.73,45.38 71.9,45.22 71.9,44.96 71.73,44.8 70,44.8 69.86,44.94 69.86,45.52 69.54,45.84 69.08,45.84 68.76,45.52 68.76,44.94 68.62,44.8 68.42,44.8 68.28,44.94 68.28,45.44 67.96,45.76 67.51,45.76 67.19,45.44 67.19,44.92 67.06,44.8 66.85,44.8 66.71,44.94 66.71,45.57 66.39,45.89 65.93,45.89 65.61,45.57 65.61,44.94 65.47,44.8 64.9,44.8 64.7,45 62.21,45 v2(61.98,45.23)
MIPI1_D3P: length 53.9
  TOP w0.109: v2(70.87,46.45) 70.68,46.26 70.68,45.46 70.3,45.07 69.09,45.07 68.97,44.96 68.97,44.69 69.09,44.57 71.68,44.57 71.97,44.28 71.97,43.81 71.67,43.51 69.18,43.51 68.97,43.31 68.97,40.16 69.29,39.84 83.43,39.84 85.89,42.31 85.89,44.28 U3.AA8 ; J1.33 60.75,44.6 60.81,44.65 61.69,44.65 v2(61.98,44.36)
  ART03 w0.102: v2(61.98,44.36) 62.31,44.69 64.57,44.69 64.78,44.49 65.6,44.49 65.92,44.81 65.92,45.44 66.06,45.58 66.26,45.58 66.4,45.44 66.4,44.81 66.72,44.49 67.19,44.49 67.49,44.8 67.49,45.31 67.63,45.46 67.83,45.46 67.98,45.31 67.98,44.81 68.3,44.49 68.75,44.49 69.07,44.81 69.07,45.39 69.21,45.53 69.41,45.53 69.55,45.39 69.55,44.81 69.87,44.49 71.86,44.49 72.2,44.83 72.2,45.34 71.86,45.68 70.82,45.68 70.64,45.86 70.64,46.22 v2(70.87,46.45)
MIPI2_CKM: length 60.9
  TOP w0.109: J1.77 60.68,53.4 60.73,53.34 61.72,53.34 v2(62.01,53.63)
  TOP w0.114: U3.W12 v1(88.5,45.59)
  ART03 w0.102: v1(88.5,45.59) 88.87,45.22 88.87,44.34 88.6,44.08 88.6,40.96 82.11,34.47 60.3,34.47 57.76,37.01 57.76,49.36 60.55,52.15 61.33,52.15 62.13,52.95 62.13,53.5 v2(62.01,53.63)
MIPI2_CKP: length 60.9
  TOP w0.109: J1.75 60.68,53 60.73,53.05 62.42,53.05 63,53.63 v2(63.12,53.63)
  TOP w0.114: U3.Y12 v1(88.5,44.94)
  ART03 w0.102: v1(88.5,44.94) 88.56,44.88 88.56,44.46 88.3,44.2 88.3,41.09 81.98,34.77 60.43,34.77 58.07,37.13 58.07,49.24 60.67,51.84 61.46,51.84 62.44,52.82 62.44,53.41 62.66,53.63 v2(63.12,53.63)
MIPI2_D0M: length 68.6
  TOP w0.109: J1.83 60.68,54.6 60.73,54.54 62.68,54.54 62.81,54.4 63.36,54.4 63.5,54.54 63.5,54.78 63.32,54.95 v2(63.23,54.95)
  TOP w0.114: U3.Y13 v1(89.8,44.94)
  ART03 w0.102: v1(89.8,44.94) 89.74,44.88 89.74,43.81 89.39,43.46 89.39,40.64 82.43,33.68 59.98,33.68 56.97,36.68 56.97,50.85 60.67,54.55 62.67,54.55 62.82,54.4 63.35,54.4 63.53,54.57 63.53,54.8 63.38,54.95 v2(63.23,54.95)
MIPI2_D0P: length 68.6
  TOP w0.109: v2(63.99,54.95) 63.78,54.75 63.78,54.42 63.48,54.12 62.69,54.12 62.56,54.25 60.73,54.25 60.68,54.2 J1.81
  TOP w0.114: U3.W13 v1(89.8,45.59)
  ART03 w0.102: v2(63.99,54.95) 63.84,54.8 63.84,54.45 63.48,54.09 62.69,54.09 62.54,54.24 60.79,54.24 57.28,50.73 57.28,36.81 60.1,33.98 82.31,33.98 89.09,40.76 89.09,43.59 89.43,43.93 89.43,45.09 89.8,45.46 v1(89.8,45.59)
MIPI2_D1M: length 53.2
  TOP w0.109: v2(63.76,52.43) 63.47,52.14 60.69,52.14 60.63,52.2 J1.71 ; U3.AB12 88.8,43.94 88.8,40.4 84.85,36.45 66.78,36.45 65.58,37.65 65.58,53.38 65.91,53.71 66.32,53.71 v2(66.53,53.93)
  ART03 w0.102: v2(63.76,52.43) 63.96,52.22 64.15,52.22 65.7,53.77 66.38,53.77 v2(66.53,53.93)
MIPI2_D1P: length 53.2
  TOP w0.109: J1.69 60.63,51.8 60.69,51.85 63.47,51.85 v2(63.76,51.56) ; U3.AA12 88.51,44.3 88.51,40.51 84.73,36.73 66.9,36.73 65.86,37.77 65.86,53.26 66.03,53.43 66.3,53.43 66.53,53.2 v2(66.53,53.06)
  ART03 w0.102: v2(66.53,53.06) 66.53,53.35 66.41,53.47 65.83,53.47 64.28,51.92 63.85,51.92 63.76,51.83 v2(63.76,51.56)
MIPI2_D2M: length 56.2
  TOP w0.109: v2(62.01,56.03) 61.72,55.74 60.73,55.74 60.68,55.8 J1.89 ; U3.AB13 89.45,43.94 89.45,39.95 85.17,35.67 66.46,35.67 64.8,37.33 64.8,55.49 65.15,55.84 65.48,55.84 v2(65.66,56.03)
  ART03 w0.102: v2(62.01,56.03) 62.18,55.85 65.49,55.85 v2(65.66,56.03)
MIPI2_D2P: length 56.2
  TOP w0.109: J1.87 60.68,55.4 60.73,55.45 61.72,55.45 v2(62.01,55.16) ; U3.AA13 89.16,44.31 89.16,40.07 85.05,35.96 66.58,35.96 65.09,37.45 65.09,55.37 65.27,55.55 65.55,55.55 65.66,55.44 v2(65.66,55.16)
  ART03 w0.102: v2(65.66,55.16) 65.66,55.34 65.45,55.55 62.16,55.55 62.01,55.39 v2(62.01,55.16)
MIPI2_D3M: length 56.3
  TOP w0.109: v2(61.88,51.23) 62.06,51.23 62.24,51.04 62.24,50.83 62.08,50.67 61.69,50.67 61.42,50.94 60.74,50.94 60.68,51 J1.65
  TOP w0.114: U3.Y11 v1(87.85,44.94)
  ART03 w0.102: v1(87.85,44.94) 87.78,44.88 87.78,41.26 81.78,35.25 60.63,35.25 58.55,37.33 58.55,48.22 60.08,49.75 61.91,49.75 62.16,50 62.16,50.95 v2(61.88,51.23)
MIPI2_D3P: length 56.4
  TOP w0.109: J1.63 60.62,50.6 60.68,50.65 61.31,50.65 61.57,50.38 62.2,50.38 62.53,50.71 62.53,51.02 v2(62.74,51.23)
  TOP w0.114: U3.W11 v1(87.85,45.59)
  ART03 w0.102: v1(87.85,45.59) 87.85,45.46 87.48,45.09 87.48,41.38 81.65,35.56 60.76,35.56 58.85,37.46 58.85,48.09 60.2,49.44 62.03,49.44 62.46,49.88 62.46,50.95 v2(62.74,51.23)
MP2143_FB: length 4.1
  BOTTOM w0.127: R194.2 R232.1 R186.2 110.27,28.32 R191.2
MUTE: length 39.7
  TOP w0.127: U3.AA14 89.81,44.3 89.81,43.82 89.74,43.75 89.74,43.32
  TOP w0.203: v1(90.05,42.71) 89.74,43.02 89.74,43.32 ; J18.78 v2(121.37,32.2)
  ART03 w0.203: v2(121.37,32.2) 117.84,32.2 111.84,38.19 95.97,38.19 v2(94.26,39.89)
  BOTTOM w0.203: v2(94.26,39.89) 91.7,39.89 90.07,41.52 90.07,42.69 v1(90.05,42.71)
MUTE_C: length 74.4
  TOP w0.203: U8.6 v2(23.47,63.26) ; v2(29.49,27.19) 31.02,28.72 31.02,55.39 37.43,61.8 v2(40.86,61.8) ; U5.5 v2(20.11,27.07)
  ART03 w0.203: v2(20.11,27.07) 20.24,27.19 v2(29.49,27.19) ; v2(23.47,63.26) 24.93,61.8 v2(40.86,61.8)
  BOTTOM w0.203: R58.1 20.1,27.08 v2(20.11,27.07) ; R169.2 v2(23.47,63.26) ; J19.78 v2(40.86,61.8)
MX0+: length 13.2
  TOP w0.254: J20.1 155.84,75.58 155.02,76.39 152.89,76.39 150.8,74.31 148.6,74.31 147.69,75.21 146.46,75.21 146.18,75.5 T1.23
MX0-: length 13.2
  TOP w0.254: T1.22 146.18,74.5 146.46,74.78 147.51,74.78 148.42,73.88 150.98,73.88 153.07,75.96 154.84,75.96 155.22,75.58 155.22,75.21 J20.2
MX1+: length 13.3
  TOP w0.254: T1.20 146.18,72.5 146.46,72.21 146.9,72.21 v2(147.12,72.43)
  ART03 w0.254: v2(147.12,72.43) 147.32,72.23 153.19,72.23 153.9,71.52 154.98,71.52 156.36,72.9 J20.3
MX1-: length 13.3
  TOP w0.254: v2(147.12,71.57) 146.9,71.78 146.46,71.78 146.18,71.5 T1.19
  ART03 w0.254: v2(147.12,71.57) 147.32,71.77 148.51,71.77 148.84,71.44 148.84,71.03 149.18,70.69 149.65,70.69 149.99,71.03 149.99,71.44 150.32,71.77 150.79,71.77 151.13,71.44 151.13,71.03 151.46,70.69 151.94,70.69 152.27,71.03 152.27,71.44 152.61,71.77 153,71.77 153.71,71.07 154.01,71.07 J20.6
MX2+: length 12.8
  TOP w0.254: J20.4 154.58,72.15 154.38,71.95 153.19,71.95 152.94,72.2 152.94,72.75 152.68,73 152.18,73 151.92,72.75 151.92,72.15 151.72,71.95 148.75,71.95 146.3,69.5 T1.17
MX2-: length 12.8
  TOP w0.254: J20.5 148.93,71.52 145.91,68.5 T1.16
MX3+: length 14.7
  TOP w0.254: T1.14 146.18,66.5 146.46,66.21 146.79,66.21 147.1,66.52 147.1,68.47 148.8,70.17 153.4,70.17 154.08,69.48 J20.7
MX3-: length 14.7
  TOP w0.254: J20.8 154.49,68.47 153.22,69.74 152.89,69.74 152.68,69.54 152.68,68.94 152.46,68.72 151.98,68.72 151.8,68.9 151.8,69.48 151.54,69.74 148.98,69.74 147.53,68.29 147.53,66.34 146.97,65.78 146.46,65.78 146.18,65.5 T1.13
NF_ALE: length 34
  TOP w0.127: U3.V1 81.51,46.56 80.17,45.23 v2(74.88,45.23) ; U7.17 v2(66.58,24.66)
  ART04 w0.127: v2(74.88,45.23) 74.58,45.23 73.63,44.27 73.63,39.98 65.33,31.69 65.33,25.91 v2(66.58,24.66)
NF_CLE: length 33.2
  TOP w0.127: v2(66.58,25.67) 66.07,25.16 U7.16 ; U3.V2 82.01,46.25 81.54,46.25 80.02,44.72 v2(75.7,44.72)
  ART04 w0.127: v2(66.58,25.67) 65.77,26.48 65.77,31.58 74.01,39.82 74.01,44.07 74.66,44.72 v2(75.7,44.72)
NF_CSN/SFC_CSN0: length 48.7
  TOP w0.127: v2(63.66,28.31) 64.01,28.66 U7.9 66.91,28.66 67.59,29.35 67.59,31.68 68.67,32.76 v2(69.02,32.76) ; U3.R1 80.23,48.51 79.89,48.17 79.89,47.96 79.51,47.58 77.06,47.58 76.23,46.75 v2(75.7,46.75) ; v2(71.38,33.07) U16.7 71.38,30.37 71.66,30.09 71.66,28.87 71.53,28.74 U4.1
  ART04 w0.127: v2(75.7,46.75) 74.48,46.75 72.48,44.76 72.48,40.46 70.69,38.66 70.68,38.66 62.77,30.75 62.77,29.2 v2(63.66,28.31)
  BOTTOM w0.127: v2(69.02,32.76) 69.33,33.07 v2(71.38,33.07) R139.1
NF_DQ0/SFC_HOLD_IO3: length 48.5
  TOP w0.127: U3.R4 83.62,48.51 v1(83.95,48.19) ; v2(85.75,23.16) U7.29 82.16,23.16 80.8,24.53 80.8,27.95 v2(80.04,28.72) 80.04,29.48 79,30.52 U16.1
  ART04 w0.127: v1(83.95,48.19) 83.31,48.83 82.19,48.83 81.18,47.82 81.18,46.5 79.85,45.16 79.85,33.89 81.31,32.43 81.31,29.02 82.71,27.62 82.71,23.89 83.43,23.16 v2(85.75,23.16)
  BOTTOM w0.127: R212.2 80.02,28.69 v2(80.04,28.72) R138.1
NF_DQ1/SFC_CLK: length 47.9
  TOP w0.127: v2(81.82,24.4) 82.55,23.66 U7.30 85.98,23.66 86.26,23.38 86.26,21.35 85.5,20.59 79.28,20.59 79,20.87 U16.16 79,23.54 79.79,24.32 79.79,25.8 79.38,26.2 U4.6
  ART04 w0.127: v1(80.42,48.1) 80.42,47.64 78.58,45.8 78.58,31.7 79.53,30.75 79.53,26.68 v2(81.82,24.4)
  BOTTOM w0.127: R801.1 80.51,48.19 v1(80.42,48.1)
NF_DQ2: length 29.3
  TOP w0.127: v1(83.3,48.19) 82.97,47.87 U3.T3 ; U7.31 83.23,24.16 v2(83.22,24.14)
  ART04 w0.127: v2(83.22,24.14) 83.22,27.65 81.69,29.18 81.69,32.59 80.23,34.05 80.23,45.04 81.69,46.5 81.69,47.79 82.47,48.57 82.92,48.57 v1(83.3,48.19)
NF_DQ3/SFC_SDO_IO0: length 48
  TOP w0.127: U4.5 77.86,24.93 77.73,24.81 U16.15 77.73,20.74 78.39,20.08 85.76,20.08 86.8,21.12 86.8,23.87 86,24.66 U7.32 83.46,24.66 v2(82.2,25.92) ; U3.T2 82,47.54 81.34,47.54 80.68,46.88 v1(80.42,46.88)
  ART04 w0.127: v2(82.2,25.92) 82.2,27.45 80.17,29.48 80.17,30.84 79.09,31.92 79.09,45.59 80.37,46.88 v1(80.42,46.88)
NF_DQ4: length 24.4
  TOP w0.127: v1(79.9,45.86) 80.42,45.86 81.45,46.89 82.65,46.89 U3.U3 ; U7.41 81.5,29.16 v2(80.8,29.86)
  ART04 w0.127: v2(80.8,29.86) 80.8,30.75 79.47,32.08 79.47,45.42 79.9,45.85 v1(79.9,45.86)
NF_DQ5: length 21.3
  TOP w0.127: U3.T4 v1(83.3,47.54) ; U7.42 83.03,29.66 v2(82.96,29.73)
  ART04 w0.127: v1(83.3,47.54) 81.37,45.61 81.37,34.7 82.96,33.11 v2(82.96,29.73)
NF_DQ6: length 21.7
  TOP w0.127: v2(86.77,30.88) 86.06,30.16 U7.43 ; v1(83.95,47.54) 83.62,47.22 83.62,47.21 U3.U4
  ART04 w0.127: v2(86.77,30.88) 86.77,31 83.34,34.43 83.34,43.3 82.92,43.72 82.92,45.18 83.95,46.21 v1(83.95,47.54)
NF_DQ7: length 18.7
  TOP w0.127: U7.44 85.67,30.66 v2(85.88,30.88) ; U3.V3 v1(82.65,46.24)
  ART04 w0.127: v2(85.88,30.88) 85.88,31.27 82.5,34.65 82.5,46.09 v1(82.65,46.24)
NF_RDY/SFC_WP_IO2: length 50.3
  TOP w0.127: v2(75.7,45.73) 79.18,45.73 79.69,46.24 80.42,46.24 81.39,47.21 U3.U1 ; R137.2 70.13,20.59 v2(70.11,20.61) U16.9 70.11,23.41 69.83,23.69 69.83,26 70.03,26.2 U4.3 ; v2(66.38,29.66) U7.7 64.21,29.66 v2(63.66,30.22) R140.1
  ART03 w0.127: v2(66.38,29.66) 66.38,28.15 70.11,24.42 v2(70.11,20.61)
  ART04 w0.127: v2(63.66,30.22) 63.66,30.56 71,37.9 71.01,37.9 73.25,40.14 73.25,44.44 74.54,45.73 v2(75.7,45.73)
NF_REN/SFC_SDI_IO1: length 46.1
  TOP w0.127: U4.2 69.98,27.47 69.63,27.83 69.63,29.61 70.11,30.09 U16.8 70.11,32.91 69.75,33.26 68.54,33.26 67.09,31.81 67.09,29.48 66.77,29.16 U7.8 63.82,29.16 v2(63.72,29.27) ; U3.T1 81.24,47.86 80.78,47.4 80.31,47.4 79.15,46.24 v2(74.88,46.24)
  ART04 w0.127: v2(74.88,46.24) 74.51,46.24 72.86,44.6 72.86,40.3 70.85,38.28 70.84,38.28 63.15,30.59 63.15,29.84 v2(63.72,29.27)
NF_WEN: length 33.3
  TOP w0.127: U7.18 66.31,24.16 66.58,23.89 v2(66.58,23.64) ; v2(74.88,44.21) 79.97,44.21 U3.W1
  ART04 w0.127: v2(66.58,23.64) 67.14,24.2 67.14,32.41 74.39,39.67 74.39,43.72 v2(74.88,44.21)
P_IRIS_CONTROL1: length 56.8
  TOP w0.127: v1(92.31,41.32) 93.26,42.27 93.26,43.36 93.7,43.8 93.7,44.29 U3.AA19 ; v2(60.36,17.41) 61.76,16.01 U20.14
  ART03 w0.127: v2(60.36,17.41) 60.99,16.78 66.71,16.78 67.59,15.89 77.63,15.89 90.64,28.91 90.64,38.78 91.83,39.96 91.83,40.83 v1(92.31,41.32)
P_IRIS_CONTROL2: length 51.6
  TOP w0.127: v1(92.36,43.51) 92.36,43.6 U3.AB18 ; U20.13 62.15,16.51 v2(61.24,17.41)
  ART03 w0.127: v1(92.36,43.51) 90.51,41.66 90.51,40.29 89.5,39.29 89.5,29.38 77.53,17.41 67.09,17.41 66.83,17.16 61.5,17.16 v2(61.24,17.41)
P_IRIS_CONTROL3: length 45.7
  TOP w0.127: U20.7 67.84,16.01 v2(68.23,16.4) ; U3.AB19 93.37,43.82 93.02,43.46 93.02,42.69 v1(92.31,41.98)
  ART03 w0.127: v1(92.31,41.98) 91.32,40.99 91.32,39.99 90.26,38.94 90.26,29.07 77.6,16.4 v2(68.23,16.4)
P_IRIS_CONTROL4: length 45.8
  TOP w0.127: U20.8 67.07,16.51 v2(67.47,16.91) ; U3.AA18 93.04,44.3 93.04,43.83 92.77,43.55 92.77,43.09 v1(92.31,42.64)
  ART03 w0.127: v1(92.31,42.64) 90.94,41.26 90.94,40.18 89.88,39.13 89.88,29.22 77.57,16.91 v2(67.47,16.91)
PER_RSTN: length 93.9
  TOP w0.127: U13.4 95.47,29.67 v2(96.04,30.24) ; R36.1 v2(136.7,42.89)
  ART03 w0.127: v2(96.04,30.24) 96.25,30.44 98,30.44 98.84,29.61 113.62,29.61 124.82,18.4 142.61,18.4 149.73,25.52 149.73,42.01 v2(149.76,42.05)
  ART04 w0.127: v2(149.76,42.05) 137.44,42.05 136.7,42.79 v2(136.7,42.89)
PHY_AD2: length 2.8
  TOP w0.127: R141.1 R1005.2 119.41,76.09 119.93,75.57 U2.13
REG_OUT_1.05V: length 1.6
  BOTTOM w0.305: C54.1 132.34,77.37 ; C54.1 131.82,76.85 ; C54.1 132.34,76.33
RGMII_RX_CLK: length 8.3
  TOP w0.127: R1004.1 117.28,72.4 116.26,71.39 111.76,71.39 v2(111.66,71.29)
  BOTTOM w0.127: U10.42 v2(111.66,71.29)
RGMII_RX_CLK/VO_DATA11: length 23
  TOP w0.127: v2(102.65,72.28) 94.69,64.32 94.69,59.59 93.71,58.61 93.71,57.5 93.5,57.29 93.25,57.29 93.04,57.09 93.04,56.64 U3.C18
  BOTTOM w0.127: U10.8 104.73,71.79 104.62,71.9 103.03,71.9 v2(102.65,72.28)
RGMII_RX_DV/PHY_AD2: length 8.2
  TOP w0.127: v2(113.7,76.79) 114.4,76.09 R1005.1
  BOTTOM w0.127: v2(113.7,76.79) U10.31
RGMII_RX_DV/PHY_AD2/VO_DATA15: length 25.2
  TOP w0.127: v2(101.63,75.29) 99.93,73.59 99.93,72.43 92.66,65.16 92.66,60.1 92.07,59.52 U3.A17
  BOTTOM w0.127: U10.15 v2(101.63,75.29)
RGMII_RXD0/SELRGV: length 43.4
  TOP w0.127: U3.B17 92.4,57.29 92.4,59.34 93.04,59.98 93.04,65 100.49,72.45 v2(100.49,72.66) ; v2(117.19,74.99) 117.27,75.07 R1000.1
  ART03 w0.127: v2(117.19,74.99) 116.32,74.99 110.69,80.62 106.42,80.62 102.65,76.85 102.65,75.58 100.49,73.42 v2(100.49,72.66)
RGMII_RXD1/TXDLY: length 4.2
  TOP w0.127: v2(111.54,76.29) 112.73,76.29 113.42,75.61 R1001.1
  BOTTOM w0.127: U10.32 v2(111.54,76.29)
RGMII_RXD1/TXDLY/VO_DATA14: length 24.3
  TOP w0.127: v2(102.77,74.79) 101.86,74.79 101.25,74.18 101.25,72.68 93.42,64.85 93.42,59.85 92.72,59.15 U3.A18
  BOTTOM w0.127: U10.14 v2(102.77,74.79)
RGMII_RXD2/AN0: length 8.2
  TOP w0.127: R1002.1 117.04,73.8 116.79,74.06 114.58,74.06 114.2,74.44 v2(112.04,74.44)
  BOTTOM w0.127: v2(112.04,74.44) 111.9,74.29 U10.36
RGMII_RXD2/AN0/VO_DATA13: length 24
  TOP w0.127: U3.B18 92.72,57.15 93.06,57.48 93.06,58.98 93.8,59.72 93.8,64.69 101.77,72.66 v2(101.77,73.78)
  BOTTOM w0.127: v2(101.77,73.78) 101.78,73.79 U10.12
RGMII_RXD3/AN1: length 6.3
  TOP w0.127: R1003.1 115.58,72.94 115.47,73.04 114.58,73.04 113.82,73.8 v2(112.81,73.8)
  BOTTOM w0.127: U10.37 112.79,73.79 v2(112.81,73.8)
RGMII_RXD3/AN1/VO_DATA12: length 22
  TOP w0.127: v2(102.77,73.29) 102.77,73.12 94.18,64.53 94.18,59.59 93.37,58.79 U3.A19
  BOTTOM w0.127: U10.11 v2(102.77,73.29)
RGMII_TX_CLK: length 17.4
  TOP w0.127: U2.22 119.7,71.97 119.63,71.9 117.49,71.9 116.47,70.88 112.04,70.88 110.65,69.48 110.65,66.82 110.16,66.33 108.33,66.33 v2(107.85,66.82)
  BOTTOM w0.127: U10.52 v2(107.85,66.82)
RGMII_TX_CLK/VO_DE: length 17.7
  TOP w0.127: v2(99.47,68.21) 95.28,64.02 R19.1
  ART03 w0.127: v2(99.47,68.21) 100.36,67.32 106.21,67.32 v2(106.85,66.69)
  BOTTOM w0.127: v2(106.85,66.69) U10.54
RGMII_TX_EN: length 33.4
  TOP w0.127: U2.27 121.76,69.99 121.37,69.6 118.04,69.6 113.75,65.32 101.27,65.32 97.95,61.99 v2(97.82,61.99)
  BOTTOM w0.127: R90.1 96.8,61.99 v2(97.82,61.99)
RGMII_TXD0: length 14.5
  TOP w0.127: v2(112.43,70.37) 113.37,70.37 113.52,70.22 113.52,69.76 113.67,69.61 113.88,69.61 114.03,69.76 114.03,70.22 114.17,70.37 114.39,70.37 114.53,70.22 114.53,69.76 114.68,69.61 114.89,69.61 115.04,69.76 115.04,70.22 115.19,70.37 115.4,70.37 115.55,70.22 115.55,69.76 115.7,69.61 115.91,69.61 116.06,69.76 116.06,70.22 116.21,70.37 116.68,70.37 117.7,71.39 119.61,71.39 119.79,71.57 U2.23
  BOTTOM w0.127: v2(112.43,70.37) 112.01,70.79 U10.43
RGMII_TXD0/VO_DATA10: length 13.4
  TOP w0.127: R8.1 95.79,63.55 102.88,70.63 v2(102.88,71.29)
  BOTTOM w0.127: U10.7 v2(102.88,71.29)
RGMII_TXD1: length 19.5
  TOP w0.127: U2.24 119.83,71.17 119.66,71.01 118.14,71.01 v2(118.01,70.88)
  ART03 w0.127: v2(106.35,79.35) 107.38,79.35 107.38,79.35 107.84,79.81 109.8,79.81 112.77,76.84 112.77,75.97 114.72,74.02 115.03,74.02 118.01,71.04 v2(118.01,70.88)
  BOTTOM w0.127: v2(106.35,79.35) U10.22
RGMII_TXD1/VO_VS: length 20.6
  TOP w0.127: R20.1 96.3,63.51 103.36,70.58 103.36,76.77 103.35,76.78 v2(103.35,76.85)
  BOTTOM w0.127: U10.19 103.79,77.29 v2(103.35,76.85)
RGMII_TXD2: length 15.1
  TOP w0.127: U2.25 120.82,70.63 118.52,70.63 116.62,68.72 115.52,68.72 115.37,68.57 115.37,68.11 115.23,67.96 115.02,67.96 114.87,68.11 114.87,68.57 114.72,68.72 114.51,68.72 114.36,68.57 114.36,68.11 114.21,67.96 114,67.96 113.85,68.11 113.85,68.57 113.7,68.72 113.49,68.72 113.34,68.57 113.34,68.11 113.19,67.96 v2(112.43,67.96)
  BOTTOM w0.127: v2(112.43,67.96) 111.6,68.79 U10.47
RGMII_TXD2/VO_DATA9: length 13.2
  TOP w0.127: v2(97.57,63.9) 96.83,63.16 R25.1
  ART03 w0.127: v2(104.3,69.1) 98.84,69.1 97.57,67.83 v2(97.57,63.9)
  BOTTOM w0.127: U10.3 104.48,69.29 v2(104.3,69.1)
RGMII_TXD3: length 21.3
  TOP w0.127: v2(119.03,70.12) 119.17,69.98 121.18,69.98 121.36,70.16 U2.26
  ART03 w0.127: v2(107.22,79.9) 107.51,80.19 109.96,80.19 113.15,77 113.15,76.6 114.68,75.07 115,75.07 117.38,72.69 117.38,72.5 119.03,70.85 v2(119.03,70.12)
  BOTTOM w0.127: v2(107.22,79.9) 106.85,79.53 U10.23
RGMII_TXD3/VO_HS: length 20.3
  TOP w0.127: v2(104.35,77.79) 104.33,77.79 103.82,77.28 103.82,68.91 97.31,62.4 R88.1
  BOTTOM w0.127: U10.20 v2(104.35,77.79)
RS485_A_D+: length 33.2
  TOP w0.127: R889.2 36.2,77.48 36.2,77.93 35.14,78.99 19.84,78.99 18.78,80.05 17.05,80.05 R18.1 16.53,80.06 15.87,80.06 D13.1 15.24,80 11.94,80 J17.4 J17.3
RS485_B_D-: length 33.8
  TOP w0.127: J17.1 J17.2 11.96,80.29 15.1,80.29 D14.2 15.89,80.35 16.54,80.35 R18.2 17.06,80.34 18.9,80.34 19.96,79.28 35.26,79.28 36.49,78.05 36.49,77.5 R888.2
RXDLY: length 2
  TOP w0.127: U2.32 123.76,68.52 R147.2
SAR_ADC0: length 49.9
  TOP w0.127: U3.W2 82.32,45.91 v1(82,45.59)
  ART04 w0.127: J50.2 102.63,11.1 101.88,11.85 101.88,16.5 101.43,16.96 99.21,16.96 95.52,20.65 90.44,20.65 84.49,26.6 84.49,32.13 81.75,34.86 81.75,44 81.62,44.13 81.62,45.21 v1(82,45.59)
SDIO0_CARD_DETECT: length 62.3
  TOP w0.127: v2(103.41,46.88) 103.28,46.75 100.41,46.75 100.25,46.92 98.1,46.92 97.47,47.54 95,47.54 U3.T21
  ART03 w0.127: v2(103.41,46.88) 103.61,47.08 106.04,47.08 106.48,46.64 113.47,46.64 113.82,46.28 120.01,46.28 126.78,39.52 126.78,38.72 130.3,35.19 137.95,35.19 v2(138.08,35.07)
  BOTTOM w0.127: v2(138.08,35.07) 139.6,36.59 144.68,36.59 145.32,37.23 147.22,37.23 147.4,37.4 R159.2 J13.12
SDIO0_CARD_POWER_EN: length 46.5
  TOP w0.127: v1(93.7,50.14) 93.37,49.81 U3.N19
  ART03 w0.127: v2(132.54,37.94) 131.97,37.94 121.09,48.82 114.88,48.82 113.96,49.74 94.1,49.74 v1(93.7,50.14)
  BOTTOM w0.127: v2(132.54,37.94) R56.1 R57.1
SDIO0_CCLK_OUT: length 56.6
  TOP w0.127: v2(102.65,48.78) 102.14,48.27 R26.2
  ART03 w0.127: v2(102.65,48.78) 103.08,48.35 106.63,48.35 107.08,47.91 113.99,47.91 114.35,47.55 120.56,47.55 128.05,40.07 128.05,39.25 130.83,36.46 139.86,36.46 140.49,35.83 v2(140.49,34.43)
  BOTTOM w0.127: v2(140.49,34.43) 140.63,34.57 147.43,34.57 147.66,34.79 148.21,34.79 148.49,34.51 148.49,33.67 148.78,33.38 J13.5
SDIO0_CCMD: length 61.3
  TOP w0.127: R784.2 v2(100.23,48.78)
  ART03 w0.127: v2(141.93,31.13) 141.38,31.68 141.38,36.28 140.31,37.35 132.02,37.35 120.93,48.44 114.72,48.44 114.36,48.8 107.78,48.8 107.25,49.33 100.65,49.33 100.23,48.91 v2(100.23,48.78)
  BOTTOM w0.127: J13.3 R164.2 147.4,31.46 147.11,31.75 142.55,31.75 v2(141.93,31.13)
SDIO0_CDATA0: length 56.3
  TOP w0.127: R776.2 v2(100.23,47.77)
  ART03 w0.127: v2(139.98,35.45) 139.48,35.96 130.62,35.96 127.54,39.04 127.54,39.83 120.33,47.04 114.14,47.04 113.78,47.4 106.8,47.4 106.35,47.84 102.87,47.84 102.78,47.93 100.36,47.93 100.23,47.81 v2(100.23,47.77)
  BOTTOM w0.127: J13.7 R162.2 147.4,35.37 147.1,35.07 140.36,35.07 v2(139.98,35.45)
SDIO0_CDATA1: length 54.8
  TOP w0.127: R778.2 102.42,47.26 v2(102.49,47.34)
  ART03 w0.127: v2(139.1,35.07) 138.59,35.57 130.46,35.57 127.16,38.88 127.16,39.68 120.17,46.66 113.98,46.66 113.62,47.02 106.64,47.02 106.2,47.46 102.62,47.46 v2(102.49,47.34)
  BOTTOM w0.127: v2(139.1,35.07) 139.1,35.45 139.74,36.09 147.23,36.09 147.4,36.26 R161.2 J13.8
SDIO0_CDATA2: length 61.8
  TOP w0.127: R780.2 v2(102.39,50.31)
  ART03 w0.127: v2(142.4,28.34) 142.4,31.38 141.76,32.02 141.76,36.44 139.8,38.41 132.04,38.41 121.25,49.2 115.03,49.2 114.12,50.12 102.58,50.12 v2(102.39,50.31)
  BOTTOM w0.127: v2(142.4,28.34) 142.44,28.37 147.01,28.37 147.4,28.77 R160.2 J13.1
SDIO0_CDATA3: length 60.1
  TOP w0.127: v2(103.66,48.86) 103.23,49.29 R782.2
  ART03 w0.127: v2(140.87,31.13) 141,31.26 141,36.13 140.15,36.97 131.04,36.97 128.63,39.38 128.63,40.2 120.77,48.06 114.56,48.06 114.2,48.41 107.62,48.41 107.18,48.86 v2(103.66,48.86)
  BOTTOM w0.127: J13.2 R163.2 147.4,29.78 147.19,29.57 142.43,29.57 v2(140.87,31.13)
SDIO0_VOUT: length 75.9
  TOP w0.254: v1(93.7,48.84) 94.02,49.16 U3.P20
  ART03 w0.381: v2(140.62,28.59) 140.62,29.99 135.92,34.69 130.09,34.69 126.27,38.51 126.27,39.31 120.01,45.57 102.94,45.57 101.43,47.08 99.85,47.08 98.6,48.33 94.14,48.33 93.7,48.77 v1(93.7,48.84)
  ART04 w0.381: v2(145.9,36.68) v2(145.9,35.58) 144.94,34.62 144.94,30.72 145.38,30.28 v2(145.92,30.28) 145.93,30.27 v2(145.93,28.84) 143.93,28.84 143.29,29.48 141.51,29.48 v2(140.62,28.59)
  BOTTOM w0.381: v2(145.92,30.28) 146.11,30.08 R163.1 R164.1 ; v2(145.93,28.84) 146.07,28.98 R160.1 ; R161.1 v2(145.9,36.68) ; R162.1 v2(145.9,35.58)
SDIO1_CARD_DETECT: length 76.8
  TOP w0.127: J12.12 R158.2 147.4,24.58 146.84,24.02 v2(145.06,24.02) ; v2(99.34,52.85) 99.22,52.72 97.47,52.72 96.19,51.44 94.54,51.44 94.3,51.2 94.1,51.2 U3.L20
  ART03 w0.127: v2(99.34,52.85) 99.65,53.15 103.28,53.15 103.7,53.57 106.75,53.57 107.35,52.97 114.84,52.97 115.16,53.29 121.31,53.29 133.12,41.48 140.08,41.48 144.52,37.05 144.52,24.56 v2(145.06,24.02)
SDIO1_CARD_POWER_EN: length 74.7
  TOP w0.127: R54.1 R55.1 144.28,24.32 v2(144.99,25.03) ; v2(99.47,53.86) 99.09,53.86 98.71,53.48 97.15,53.48 96.19,52.52 95.74,52.52 95.52,52.73 94.48,52.73 94.35,52.61 94.35,52.26 94.09,52 94.09,51.83 U3.K20
  ART03 w0.127: v2(99.47,53.86) 99.76,54.16 120.99,54.16 133.28,41.86 140.24,41.86 144.9,37.2 144.9,25.12 v2(144.99,25.03)
SDIO1_CCLK_OUT: length 74.6
  TOP w0.127: v2(145.57,27.9) 145.9,27.57 147.99,27.57 148.24,27.83 148.24,28.72 148.6,29.08 J12.5
  ART03 w0.127: v2(145.57,27.9) 145.41,28.07 145.41,37.52 140.56,42.37 133.57,42.37 129.82,46.12 129.82,46.75 121.91,54.66 99.1,54.66 v2(98.43,53.99)
  BOTTOM w0.127: R27.2 96.8,50.43 98.43,52.06 v2(98.43,53.99)
SDIO1_CCMD: length 63.8
  TOP w0.127: J12.3 R153.2 147.4,30.93 147.22,30.75 143.29,30.75 v2(142.91,31.13) ; v2(102.52,51.32) R786.2
  ART03 w0.127: v2(102.52,51.32) 103.34,50.5 109.82,50.5 110.39,51.07 114.55,51.07 115.35,50.28 115.35,49.72 115.49,49.58 115.73,49.58 115.85,49.71 115.85,50.03 115.98,50.16 116.22,50.16 116.36,50.01 116.36,49.73 116.51,49.58 116.72,49.58 116.87,49.73 116.87,50.01 117.02,50.16 117.23,50.16 117.38,50.01 117.38,49.73 117.53,49.58 117.74,49.58 117.89,49.73 117.89,50.01 118.04,50.16 118.25,50.16 118.4,50.01 118.4,49.73 118.55,49.58 120.25,49.58 120.4,49.73 120.4,50.01 120.55,50.16 120.76,50.16 120.91,50.01 120.91,49.73 121.06,49.58 121.4,49.58 132.2,38.79 140.08,38.79 142.14,36.73 142.14,32.27 142.91,31.51 v2(142.91,31.13)
SDIO1_CDATA0: length 68.1
  TOP w0.127: R884.2 102.9,49.8 103.54,50.43 v2(103.54,51.07) ; J12.7 R155.2 147.4,26.48 147.22,26.3 v2(143.41,26.3)
  ART03 w0.127: v2(143.41,26.3) 143.16,26.56 143.16,28.84 143.41,29.1 143.41,31.76 142.52,32.65 142.52,36.88 140.24,39.17 132.36,39.17 120.99,50.54 115.62,50.54 114.71,51.45 110.14,51.45 109.57,50.88 103.73,50.88 v2(103.54,51.07)
